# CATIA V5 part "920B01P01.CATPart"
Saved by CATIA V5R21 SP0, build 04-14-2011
Part number: 920B01P01
Bounding box of the stored display mesh (mm): x -17.1 to 17.1, y -76.2 to 76.2, z -4.4 to 8.9
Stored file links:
  C:\Users\ALI OZGUN\Desktop\alhan\920B01P01.CATPart
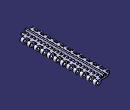
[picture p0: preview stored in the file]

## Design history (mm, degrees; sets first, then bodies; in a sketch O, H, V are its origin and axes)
Body1 (main body)
  Sketch1 on zx-plane, origin (0, 0, 0), H (-1, 0, 0), V (0, 0, 1)
    construction line L1 (-12.7, 0) -> (12.7, 0)
    point P1 (-12.7, 0)
    line L2 (-12.7, 4.4) -> (12.7, 4.4)
    line L3 (12.7, -4.4) -> (-12.7, -4.4)
    arc A1 centre (12.7, 0) radius 4.4 from (12.7, 4.4) to (12.7, -4.4) cw
    arc A2 centre (-12.7, 0) radius 4.4 from (-12.7, -4.4) to (-12.7, 4.4) cw
    distance L1 L2 = 4.4
    length L1 = 25.4
    distance P1 V = 12.7
    coincidence: P1 H
    horizontal: L1 H
    tangency: A1 L2, A2 L2, A1 L3, A2 L3
  Pad1: profile Sketch1, direction (0, 1, 0), length 76.2, mirrored extent
  Sketch2 on face of Pad1 from Sketch1.L2, origin (0, 0, 4.4), H (1, 0, 0), V (0, 1, 0)
    line L1 (-22.3127, -63.5) -> (-9.75, -63.5)
    line L2 (-9.75, -63.5) -> (-9.75, -70.6)
    line L3 (-9.75, -70.6) -> (-22.3127, -70.6)
    line L4 (-22.3127, -70.6) -> (-22.3127, -63.5)
    line L5 (24.6678, -76.95) -> (9.75, -76.95)
    line L6 (9.75, -76.95) -> (9.75, -69.85)
    line L7 (9.75, -69.85) -> (24.6678, -69.85)
    line L8 (24.6678, -69.85) -> (24.6678, -76.95)
    reference projected line E1 (-12.7, -76.2) -> (12.7, -76.2) from edge [start face of Pad1 | face of Pad1 from Sketch1.L2]
    reference projected line E2 (-12.7, -76.2) -> (12.7, -76.2) from edge [start face of Pad1 | face of Pad1 from Sketch1.L2]
    distance L3 E1 = 5.6
    length L4 = 7.1
    distance L7 L5 = 7.1
    distance L5 E2 = 0.75
    distance L2 L6 = 19.5
    distance L2 V = 9.75
    horizontal: L1 H, L3 H, L5 H, L7 H
    vertical: L2 V, L4 V, L6 V, L8 V
  Pocket1: profile Sketch2, direction (0, 0, -1), length 76.2
  RectPattern1: of Pocket1, direction 1 instances 12, spacing 12.7, along axis of face of Pad1 from Sketch1.A2
  Sketch3 on face of Pad1 from Sketch1.L3, origin (0, 0, -4.4), H (1, 0, 0), V (0, -1, 0)
    line L1 (-7, 90.4553) -> (7, 90.4553)
    line L2 (7, 90.4553) -> (7, -88.0088)
    line L3 (7, -88.0088) -> (-7, -88.0088)
    line L4 (-7, -88.0088) -> (-7, 90.4553)
    length L1 = 14
    distance L4 V = 7
    horizontal: L1 H, L3 H
    vertical: L2 V, L4 V
  Pocket2: profile Sketch3, direction (0, 0, 1), length 5.8
  Fillet1: radius 2, on edge [face of Pad1 from Sketch1.L3 | face of Pocket2 from Sketch3.L2]; edge [face of Pad1 from Sketch1.L3 | face of Pocket2 from Sketch3.L4]
  Sketch4 on yz-plane, origin (0, 0, 0), H (0, 1, 0), V (0, 0, 1)
    point P3 (69.85, -4.4)
    point P5 (69.85, -4.4)
    point P7 (57.15, -4.4)
    point P9 (57.15, -4.4)
    point P11 (44.45, -4.4)
    point P13 (44.45, -4.4)
    point P15 (31.75, -4.4)
    point P16 (31.75, -4.4)
    point P18 (19.05, -4.4)
    point P19 (19.05, 1.4)
    point P20 (19.05, -4.4)
    line L1 (-76.2, -4.4) -> (-76.2, 1.4)
    line L2 (-69.85, 1.4) -> (-69.85, -4.4)
    line L3 (-69.85, -4.4) -> (-76.2, -4.4)
    line L4 (-57.15, -4.4) -> (-64.25, -4.4)
    line L5 (-64.25, -4.4) -> (-64.25, 1.4)
    line L6 (-57.15, 1.4) -> (-57.15, -4.4)
    line L7 (-44.45, -4.4) -> (-51.55, -4.4)
    line L8 (-51.55, -4.4) -> (-51.55, 1.4)
    line L9 (-44.45, 1.4) -> (-44.45, -4.4)
    line L10 (-31.75, -4.4) -> (-38.85, -4.4)
    line L11 (-38.85, -4.4) -> (-38.85, 1.4)
    line L12 (-19.05, -4.4) -> (-26.15, -4.4)
    line L13 (-26.15, -4.4) -> (-26.15, 1.4)
    line L14 (-19.05, 1.4) -> (-19.05, -4.4)
    line L15 (-6.35, -4.4) -> (-13.45, -4.4)
    line L16 (-13.45, -4.4) -> (-13.45, 1.4)
    line L17 (-6.35, 1.4) -> (-6.35, -4.4)
    line L18 (6.35, -4.4) -> (-0.75, -4.4)
    line L19 (-0.75, -4.4) -> (-0.75, 1.4)
    line L20 (6.35, 1.4) -> (6.35, -4.4)
    construction line L21 (19.05, -4.4) -> (11.95, -4.4)
    construction line L22 (11.95, -4.4) -> (11.95, 4.4)
    construction line L23 (11.95, 4.4) -> (19.05, 4.4)
    construction line L24 (19.05, 4.4) -> (19.05, -4.4)
    line L25 (19.05, 1.4) -> (19.05, -4.4)
    line L26 (19.05, -4.4) -> (11.95, -4.4)
    line L27 (11.95, -4.4) -> (11.95, 1.4)
    construction line L28 (31.75, -4.4) -> (24.65, -4.4)
    construction line L29 (24.65, -4.4) -> (24.65, 4.4)
    construction line L30 (24.65, 4.4) -> (31.75, 4.4)
    construction line L31 (31.75, 4.4) -> (31.75, -4.4)
    line L32 (31.75, -4.4) -> (24.65, -4.4)
    line L33 (24.65, -4.4) -> (24.65, 1.4)
    line L34 (31.75, 1.4) -> (31.75, -4.4)
    construction line L35 (44.45, -4.4) -> (37.35, -4.4)
    construction line L36 (37.35, -4.4) -> (37.35, 4.4)
    construction line L37 (37.35, 4.4) -> (44.45, 4.4)
    construction line L38 (44.45, 4.4) -> (44.45, -4.4)
    line L39 (44.45, -4.4) -> (37.35, -4.4)
    line L40 (37.35, -4.4) -> (37.35, 1.4)
    line L41 (44.45, 1.4) -> (44.45, -4.4)
    construction line L42 (57.15, -4.4) -> (50.05, -4.4)
    construction line L43 (50.05, -4.4) -> (50.05, 4.4)
    construction line L44 (50.05, 4.4) -> (57.15, 4.4)
    construction line L45 (57.15, 4.4) -> (57.15, -4.4)
    line L46 (57.15, -4.4) -> (50.05, -4.4)
    line L47 (50.05, -4.4) -> (50.05, 1.4)
    line L48 (57.15, 1.4) -> (57.15, -4.4)
    construction line L49 (69.85, -4.4) -> (62.75, -4.4)
    construction line L50 (62.75, -4.4) -> (62.75, 4.4)
    construction line L51 (62.75, 4.4) -> (69.85, 4.4)
    construction line L52 (69.85, 4.4) -> (69.85, -4.4)
    line L53 (69.85, 1.4) -> (69.85, -4.4)
    line L54 (69.85, -4.4) -> (62.75, -4.4)
    line L55 (62.75, -4.4) -> (62.75, 1.4)
    construction line L56 (-76.2, 1.4) -> (76.2, 1.4)
    line L57 (62.75, 1.4) -> (69.85, 1.4)
    line L58 (50.05, 1.4) -> (57.15, 1.4)
    line L59 (37.35, 1.4) -> (44.45, 1.4)
    line L60 (-76.2, 1.4) -> (-69.85, 1.4)
    point P60 (19.05, 1.4)
    line L61 (24.65, 1.4) -> (31.75, 1.4)
    point P61 (24.65, 1.4)
    point P62 (24.65, 1.4)
    point P63 (11.95, 1.4)
    point P64 (6.35, 1.4)
    point P65 (-0.75, 1.4)
    point P66 (-6.35, 1.4)
    point P67 (-13.45, 1.4)
    point P68 (-19.05, 1.4)
    point P69 (-26.15, 1.4)
    point P70 (-38.85, 1.4)
    point P71 (-44.45, 1.4)
    point P72 (-51.55, 1.4)
    point P73 (-57.15, 1.4)
    point P74 (-64.25, 1.4)
    point P75 (-69.85, 1.4)
    line L62 (-64.25, 1.4) -> (-57.15, 1.4)
    line L63 (-51.55, 1.4) -> (-44.45, 1.4)
    line L64 (-38.85, 1.4) -> (-31.75, 1.4)
    line L65 (-26.15, 1.4) -> (-19.05, 1.4)
    line L66 (-13.45, 1.4) -> (-6.35, 1.4)
    line L67 (-0.75, 1.4) -> (6.35, 1.4)
    line L68 (11.95, 1.4) -> (19.05, 1.4)
    line L69 (-31.75, 1.4) -> (-31.75, -4.4)
    coincidence: L24 P60, L29 P61, L60 L61, L56 P62, L56 P63, L56 P64, L56 P65, L56 P66, L56 P67, L56 P68, L56 P69, L56 P70, L56 P71, L56 P72, L56 P73, L56 P74, L56 P75, L60 L62, L62 L63, L63 L64, L64 L65, L65 L66, L66 L67, L67 L68, P3 P5, P7 P9, P11 P13, P15 P16, P18 P20, P19 P60, P61 P62
    vertical: L69 V
  Pocket3: profile Sketch4, direction (1, 0, 0), length 27.8
  Sketch5 on yz-plane, origin (0, 0, 0), H (0, 1, 0), V (0, 0, 1)
    line L1 (-63.5, -4.4) -> (-70.6, -4.4)
    point P1 (-63.5, -4.4)
    point P2 (-70.6, -4.4)
    line L2 (-63.5, 1.4) -> (-63.5, -4.4)
    point P3 (-63.5, 1.4)
    point P4 (-63.5, -4.4)
    line L3 (-70.6, 1.4) -> (-63.5, 1.4)
    point P5 (-70.6, 1.4)
    point P6 (-63.5, 1.4)
    line L4 (-70.6, -4.4) -> (-70.6, 1.4)
    point P7 (-70.6, -4.4)
    point P8 (-70.6, 1.4)
    line L5 (-50.8, 1.4) -> (-50.8, -4.4)
    point P9 (-50.8, 1.4)
    point P10 (-50.8, -4.4)
    line L6 (-57.9, 1.4) -> (-50.8, 1.4)
    point P11 (-57.9, 1.4)
    point P12 (-50.8, 1.4)
    line L7 (-57.9, -4.4) -> (-57.9, 1.4)
    point P13 (-57.9, -4.4)
    point P14 (-57.9, 1.4)
    line L8 (-50.8, -4.4) -> (-57.9, -4.4)
    point P15 (-50.8, -4.4)
    point P16 (-57.9, -4.4)
    line L9 (-38.1, 1.4) -> (-38.1, -4.4)
    point P17 (-38.1, 1.4)
    point P18 (-38.1, -4.4)
    line L10 (-45.2, 1.4) -> (-38.1, 1.4)
    point P19 (-45.2, 1.4)
    point P20 (-38.1, 1.4)
    line L11 (-45.2, -4.4) -> (-45.2, 1.4)
    point P21 (-45.2, -4.4)
    point P22 (-45.2, 1.4)
    line L12 (-38.1, -4.4) -> (-45.2, -4.4)
    point P23 (-38.1, -4.4)
    point P24 (-45.2, -4.4)
    line L13 (-25.4, 1.4) -> (-25.4, -4.4)
    point P25 (-25.4, 1.4)
    point P26 (-25.4, -4.4)
    line L14 (-32.5, 1.4) -> (-25.4, 1.4)
    point P27 (-32.5, 1.4)
    point P28 (-25.4, 1.4)
    line L15 (-32.5, -4.4) -> (-32.5, 1.4)
    point P29 (-32.5, -4.4)
    point P30 (-32.5, 1.4)
    line L16 (-25.4, -4.4) -> (-32.5, -4.4)
    point P31 (-25.4, -4.4)
    point P32 (-32.5, -4.4)
    line L17 (-12.7, 1.4) -> (-12.7, -4.4)
    point P33 (-12.7, 1.4)
    point P34 (-12.7, -4.4)
    line L18 (-19.8, 1.4) -> (-12.7, 1.4)
    point P35 (-19.8, 1.4)
    point P36 (-12.7, 1.4)
    line L19 (-19.8, -4.4) -> (-19.8, 1.4)
    point P37 (-19.8, -4.4)
    point P38 (-19.8, 1.4)
    line L20 (-12.7, -4.4) -> (-19.8, -4.4)
    point P39 (-12.7, -4.4)
    point P40 (-19.8, -4.4)
    line L21 (0, 1.4) -> (0, -4.4)
    point P41 (0, 1.4)
    point P42 (0, -4.4)
    line L22 (-7.1, 1.4) -> (0, 1.4)
    point P43 (-7.1, 1.4)
    point P44 (0, 1.4)
    line L23 (-7.1, -4.4) -> (-7.1, 1.4)
    point P45 (-7.1, -4.4)
    point P46 (-7.1, 1.4)
    line L24 (0, -4.4) -> (-7.1, -4.4)
    point P47 (0, -4.4)
    point P48 (-7.1, -4.4)
    line L25 (12.7, 1.4) -> (12.7, -4.4)
    point P49 (12.7, 1.4)
    point P50 (12.7, -4.4)
    line L26 (5.6, 1.4) -> (12.7, 1.4)
    point P51 (5.6, 1.4)
    point P52 (12.7, 1.4)
    line L27 (5.6, -4.4) -> (5.6, 1.4)
    point P53 (5.6, -4.4)
    point P54 (5.6, 1.4)
    line L28 (12.7, -4.4) -> (5.6, -4.4)
    point P55 (12.7, -4.4)
    point P56 (5.6, -4.4)
    line L29 (18.3, 1.4) -> (25.4, 1.4)
    point P57 (18.3, 1.4)
    point P58 (25.4, 1.4)
    line L30 (18.3, -4.4) -> (18.3, 1.4)
    point P59 (18.3, -4.4)
    point P60 (18.3, 1.4)
    line L31 (25.4, -4.4) -> (18.3, -4.4)
    point P61 (25.4, -4.4)
    point P62 (18.3, -4.4)
    line L32 (25.4, 1.4) -> (25.4, -4.4)
    point P63 (25.4, 1.4)
    point P64 (25.4, -4.4)
    line L33 (38.1, 1.4) -> (38.1, -4.4)
    point P65 (38.1, 1.4)
    point P66 (38.1, -4.4)
    line L34 (31, 1.4) -> (38.1, 1.4)
    point P67 (31, 1.4)
    point P68 (38.1, 1.4)
    line L35 (31, -4.4) -> (31, 1.4)
    point P69 (31, -4.4)
    point P70 (31, 1.4)
    line L36 (38.1, -4.4) -> (31, -4.4)
    point P71 (38.1, -4.4)
    point P72 (31, -4.4)
    line L37 (50.8, 1.4) -> (50.8, -4.4)
    point P73 (50.8, 1.4)
    point P74 (50.8, -4.4)
    line L38 (43.7, 1.4) -> (50.8, 1.4)
    point P75 (43.7, 1.4)
    point P76 (50.8, 1.4)
    line L39 (43.7, -4.4) -> (43.7, 1.4)
    point P77 (43.7, -4.4)
    point P78 (43.7, 1.4)
    line L40 (50.8, -4.4) -> (43.7, -4.4)
    point P79 (50.8, -4.4)
    point P80 (43.7, -4.4)
    line L41 (63.5, 1.4) -> (63.5, -4.4)
    point P81 (63.5, 1.4)
    point P82 (63.5, -4.4)
    line L42 (56.4, 1.4) -> (63.5, 1.4)
    point P83 (56.4, 1.4)
    point P84 (63.5, 1.4)
    line L43 (56.4, -4.4) -> (56.4, 1.4)
    point P85 (56.4, -4.4)
    point P86 (56.4, 1.4)
    line L44 (63.5, -4.4) -> (56.4, -4.4)
    point P87 (63.5, -4.4)
    point P88 (56.4, -4.4)
    line L45 (69.1, 1.4) -> (76.2, 1.4)
    point P89 (69.1, 1.4)
    point P90 (76.2, 1.4)
    line L46 (69.1, -4.4) -> (69.1, 1.4)
    point P91 (69.1, -4.4)
    point P92 (69.1, 1.4)
    line L47 (76.2, -4.4) -> (69.1, -4.4)
    point P93 (76.2, -4.4)
    point P94 (69.1, -4.4)
    line L48 (76.2, 1.4) -> (76.2, -4.4)
    point P95 (76.2, 1.4)
    point P96 (76.2, -4.4)
    distance L4 L2 = 7.1
    coincidence: P96 P93, P95 P90, P94 P91, P92 P89, P88 P85, P87 P82, P86 P83, P84 P81, P80 P77, P79 P74, P78 P75, P76 P73, P72 P69, P71 P66, P70 P67, P68 P65, P64 P61, P63 P58, P62 P59, P60 P57, P56 P53, P55 P50, P54 P51, P52 P49, P48 P45, P47 P42, P46 P43, P44 P41, P40 P37, P39 P34, P38 P35, P36 P33, P32 P29, P31 P26, P30 P27, P28 P25, P24 P21, P23 P18, P22 P19, P20 P17, P16 P13, P15 P10, P14 P11, P12 P9, P8 P5, P7 P2, P6 P3, P4 P1
    fix: L2
  Pocket4: profile Sketch5, direction (-1, 0, 0), length 27.8
  Chamfer1: length 2.5, angle 45, on edge [face of Pocket4 | face of Pocket1 from Sketch2.L6]; edge [face of Pocket4 | face of RectPattern1] (x11); edge [face of RectPattern1 | face of Pocket4] (x11); edge [face of Pocket4 | face of Pocket1 from Sketch2.L2]
  Sketch6 on zx-plane, origin (0, 0, 0), H (-1, 0, 0), V (0, 0, 1)
    circle A1 centre (12.7, 0) radius 2.3
    point P1 (12.7, 0)
    circle A2 centre (-12.7, 0) radius 2.3
    point P2 (-12.7, 0)
    reference projected arc E1 centre (12.7, 0) radius 4.4 from (12.7, -4.4) to (12.7, 4.4) ccw from edge [face of Pocket4 | face of Pad1 from Sketch1.A1]
    reference projected arc E2 centre (-12.7, 0) radius 4.4 from (-12.7, 4.4) to (-12.7, -4.4) ccw from edge [face of Pad1 from Sketch1.A2 | end face of Pad1]
    radius A1 = 2.3
    radius A2 = 2.3
    coincidence: P1 H, P2 H
    concentricity: P1 E1, A2 E2
  Pocket5: profile Sketch6, direction (0, -1, 0), length 97.8, mirrored extent
  Sketch7 on face of Pad1 from Sketch1.L2, origin (0, 0, 4.4), H (1, 0, 0), V (0, 1, 0)
    line L1 (-6.45, -71.4) -> (-6.45, -74.2)
    point P1 (-6.45, -71.4)
    point P2 (-6.45, -74.2)
    line L2 (5.95, -74.2) -> (1.25, -74.2)
    point P3 (5.95, -74.2)
    point P4 (-6.45, -74.2)
    line L3 (5.95, -74.2) -> (5.95, -71.4)
    point P5 (5.95, -74.2)
    point P6 (5.95, -71.4)
    line L4 (-6.45, -71.4) -> (-1.25, -71.4)
    point P7 (-6.45, -71.4)
    point P8 (5.95, -71.4)
    line L5 (-6.45, -65.1) -> (-6.45, -68.4)
    point P9 (-6.45, -65.1)
    point P10 (-6.45, -68.4)
    line L6 (5.95, -68.4) -> (1.25, -68.4)
    point P11 (5.95, -68.4)
    point P12 (-6.45, -68.4)
    line L7 (5.95, -68.4) -> (5.95, -65.1)
    point P13 (5.95, -68.4)
    point P14 (5.95, -65.1)
    line L8 (-6.45, -65.1) -> (-1.25, -65.1)
    point P15 (-6.45, -65.1)
    point P16 (5.95, -65.1)
    line L9 (1.25, -65.1) -> (1.25, -68.4)
    line L10 (-1.25, -74.2) -> (-1.25, -71.4)
    point P17 (-1.25, -68.4)
    line L11 (-1.25, -68.4) -> (-1.25, -65.1)
    point P19 (1.25, -71.4)
    line L12 (1.25, -71.4) -> (1.25, -74.2)
    line L13 (-1.25, -68.4) -> (-6.45, -68.4)
    line L14 (1.25, -65.1) -> (5.95, -65.1)
    point P23 (-1.25, -74.2)
    line L15 (-1.25, -74.2) -> (-6.45, -74.2)
    line L16 (1.25, -71.4) -> (5.95, -71.4)
    distance L10 L9 = 2.5
    distance L10 V = 1.25
    vertical: L9 V, L10 V, L11 V, L12 V
    coincidence: L6 P17, L10 L11, L4 P19, L9 L12, L6 L13, L8 L14, L2 P23, L2 L15, L4 L16, P1 P7, P2 P4, P3 P5, P6 P8, P9 P15, P10 P12, P11 P13, P14 P16
  Pocket6: profile Sketch7, direction (0, 0, -1), length 97.8
  RectPattern2: of Pocket6, direction 1 instances 12, spacing 12.7, along axis of face of Pad1 from Sketch1.A2
  Sketch8 on start face of Pad1, origin (0, -76.2, 0), H (1, 0, 0), V (0, 0, 1)
    projected line E1 (-1.25, 4.4) -> (-1.25, 1.4) from face of Pocket6 from Sketch7.L10
    projected line E2 (-1.25, 8.9) -> (-1.25, 4.4) from face of Pocket6 from Sketch7.L10
    projected line E3 (1.25, 1.4) -> (1.25, 4.4) from face of Pocket6 from Sketch7.L12
    projected line E4 (1.25, 4.4) -> (1.25, 8.9) from face of Pocket6 from Sketch7.L12
    line L1 (-1.25, 8.9) -> (1.25, 8.9)
    reference projected line E5 (-12.7, 4.4) -> (12.7, 4.4) from edge [start face of Pad1 | face of Pad1 from Sketch1.L2]
    projected line E6 (-12.7, 4.4) -> (9.75, 4.4) from edge [start face of Pad1 | face of Pad1 from Sketch1.L2]
    projected line E7 (-1.25, 4.4) -> (1.25, 4.4) from edge [start face of Pad1 | face of Pad1 from Sketch1.L2]
    distance L1 E5 = 4.5
    horizontal: L1 H
  Pad2: profile Sketch8, direction (0, 1, 0), up to end face of Pad1
Body2
  Solid1: linked copy from another document
  Translate1: Direction yz-plane, Length 25.4, ToTransfor Solid1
